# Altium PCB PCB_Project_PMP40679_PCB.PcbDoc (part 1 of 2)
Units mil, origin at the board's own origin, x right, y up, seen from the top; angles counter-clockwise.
Board outline 5118.11 x 3543.31 mil, 2 copper layers (Top Layer, Bottom Layer), stack 64.8 mil thick; 113 components, 55 nets, 272 pads, 364 vias.
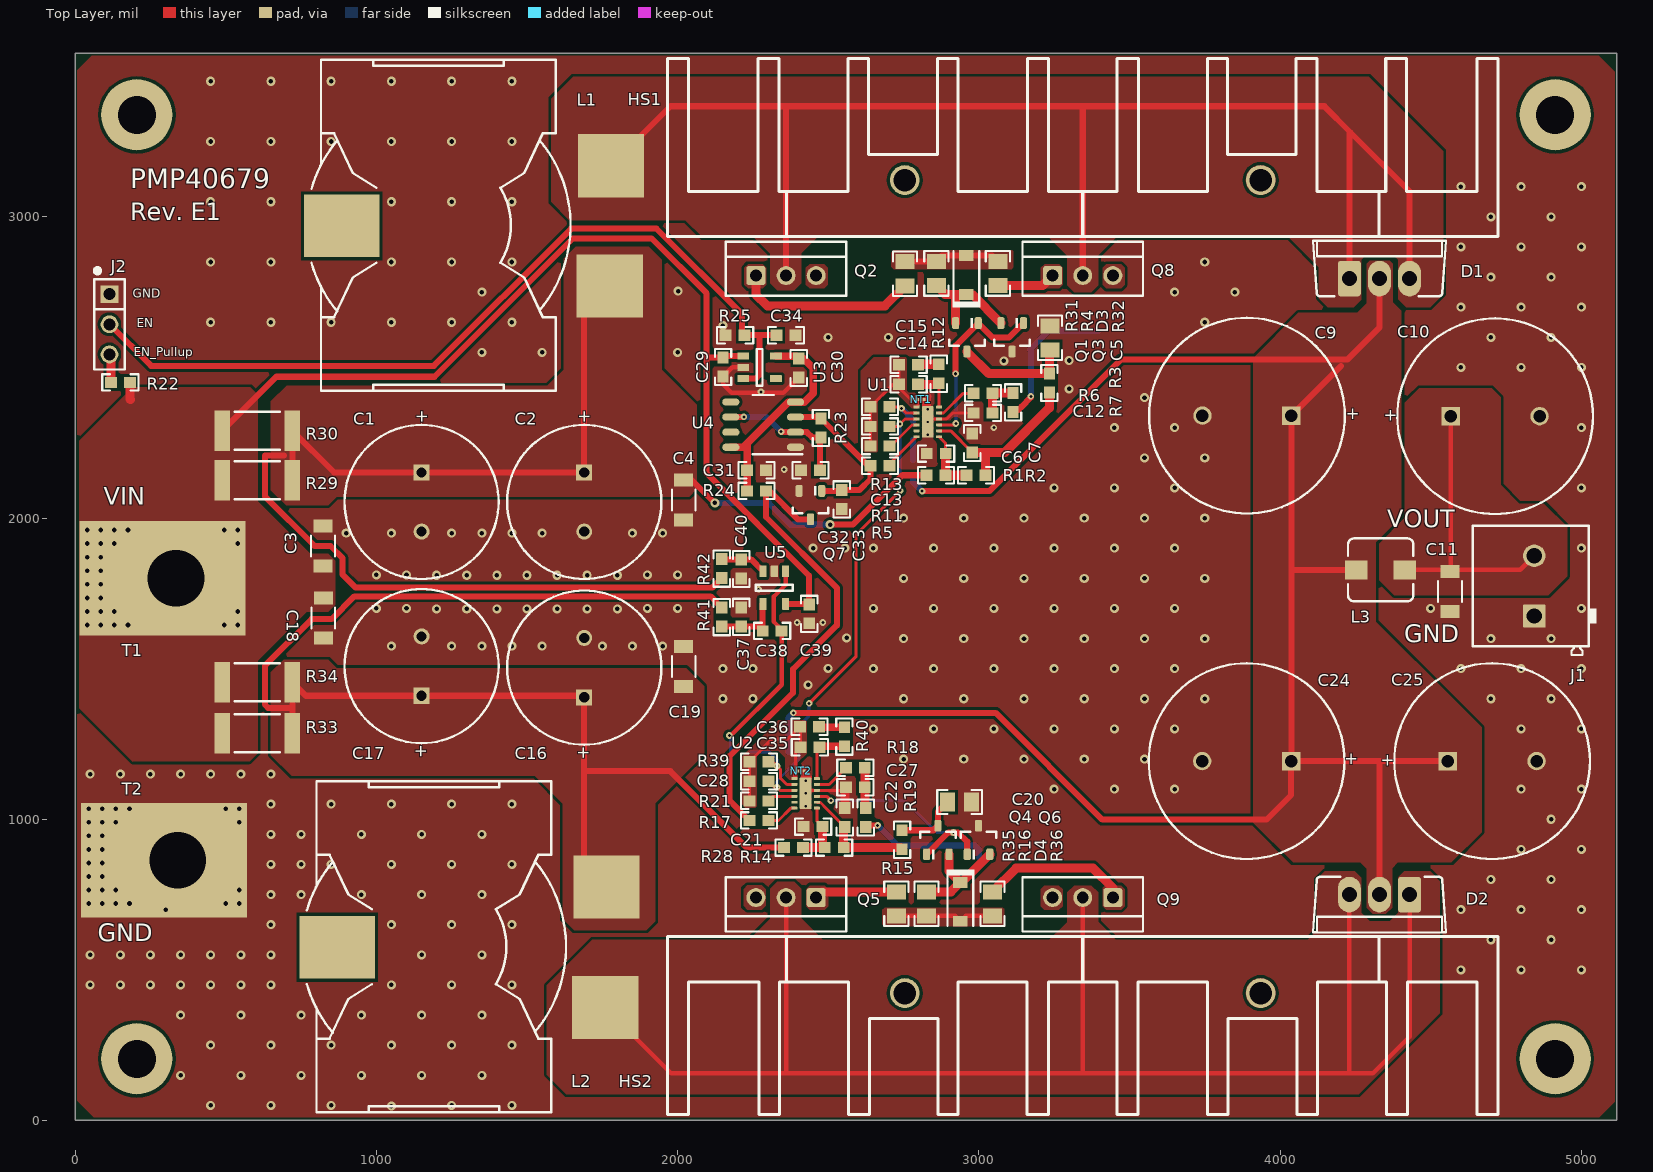
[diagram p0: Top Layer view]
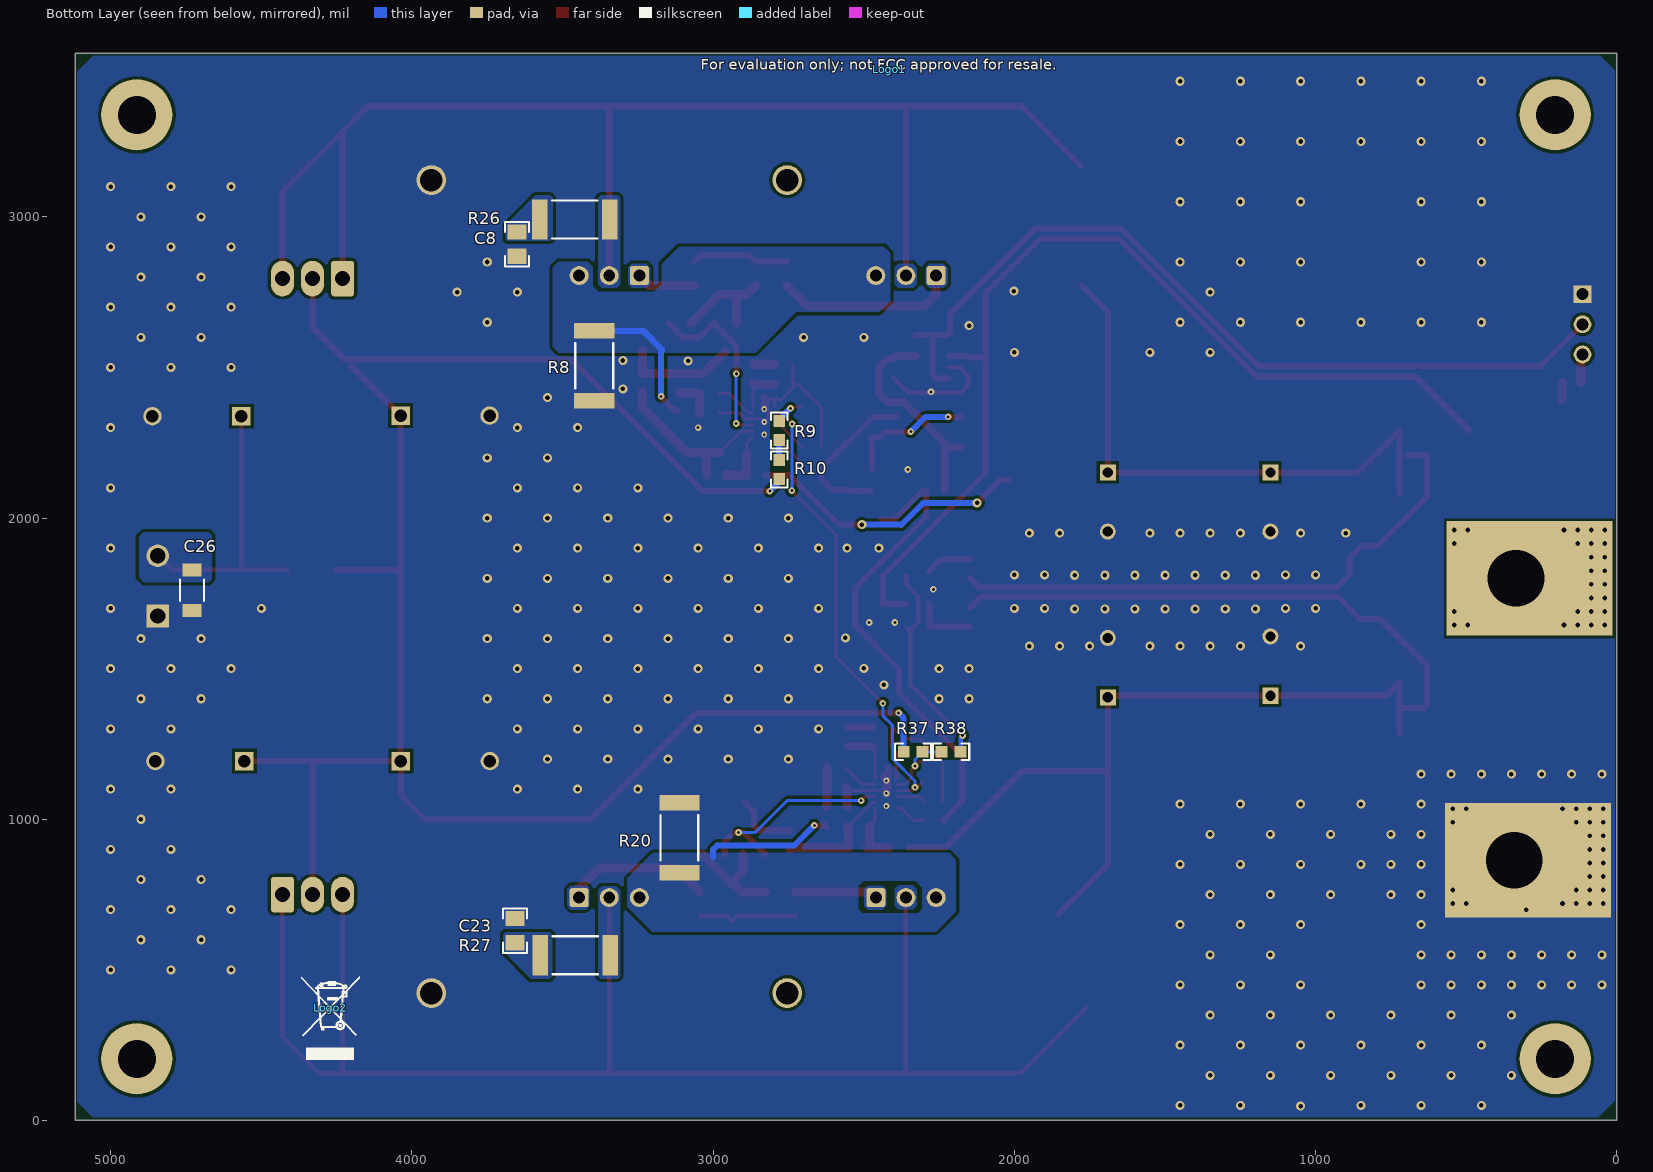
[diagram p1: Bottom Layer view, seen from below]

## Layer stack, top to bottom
Top Solder: solder mask 0.4, Solder Resist, Dk 3.5
Top Layer: signal copper 2.8
Dielectric1: core 59.2, FR-4, Dk 4.8
Bottom Layer: signal copper 2.8
Bottom Solder: solder mask 0.4, Solder Resist, Dk 3.5

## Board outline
0,0 5118.11,0 5118.11,3543.31 0,3543.31

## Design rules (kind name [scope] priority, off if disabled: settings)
AcuteAngle [All] p1: minimum=4.50000000000000E+0001 checktracksonly=FALSE
AssemblyTestPointUsage [All] p1: valid=2
Clearance Clearance_BoardEdge_MountingHoles [OnCopper and InComponentClass('Mounting Holes') vs IsKeepOut] p1: gap=40 ignorepadtopadclearanceinfootprint=FALSE except(0: Arc-Hole Track-Hole SMDPad-Hole THPad-Hole Via-Hole Fill-Hole Poly-Hole Region-Hole Text-Hole)
Clearance Clearance_BoardEdge_Poly [OnCopper and InPoly vs IsKeepOut] p2: gap=25 ignorepadtopadclearanceinfootprint=FALSE except(0: Arc-Hole Track-Hole SMDPad-Hole THPad-Hole Via-Hole Fill-Hole Poly-Hole Region-Hole Text-Hole)
Clearance Clearance_BoardEdge [OnCopper and Not InComponentClass('Logo') and not InComponentClass('FiducialMark') and not InRegion(1000,500,4000,800) and Not IsKeepout vs IsKeepOut] p3: gap=5 ignorepadtopadclearanceinfootprint=FALSE except(0: Arc-Hole Track-Hole SMDPad-Hole THPad-Hole Via-Hole Fill-Hole Poly-Hole Region-Hole Text-Hole)
Clearance Clearance_Poly [InPolygon] p4: gap=10 ignorepadtopadclearanceinfootprint=FALSE except(0: Arc-Hole Track-Hole SMDPad-Hole THPad-Hole Via-Hole Fill-Hole Poly-Hole Region-Hole Text-Hole)
Clearance [All] p5: gap=7 ignorepadtopadclearanceinfootprint=FALSE
ComponentClearance ComponentClearance_Logo [All] p1: gap=10 collisioncheckmode=3 verticalgap=10 showdistances=TRUE
ComponentClearance ComponentClearance_ScrewToNut [(HasFootprint('NY PMS 440 0025 PH')) vs (HasFootprint('Keystone_1902C'))] p2: gap=5 collisioncheckmode=3 verticalgap=10 showdistances=FALSE
ComponentClearance ComponentClearance_MountingHoles [InComponentClass('Mounting Holes')] p3: gap=10 collisioncheckmode=3 verticalgap=100000 showdistances=FALSE
ComponentClearance ComponentClearance_SmallPassives [HasFootprint('0201*') or HasFootprint('0402*') or HasFootprint('0508') or HasFootprint('0603*') or HasFootprint('0612') or HasFootprint('0805*') or HasFootprint('0815*') or HasFootprint('0830*') or HasFootprint('1206*') or HasFootprint('1210*') or HasFootprint('1808*') or HasFootprint('1812*') or HasFootprint('1825*') or HasFootprint('2010*') or HasFootprint('2220*') or HasFootprint('2225*') or HasFootprint('2512*') or HasFootprint('2728*') or HasFootprint('3518*') vs HasFootprint('0201*') or HasFootprint('0402*') or HasFootprint('0508') or HasFootprint('0603*') or HasFootprint('0612') or HasFootprint('0805*') or HasFootprint('0815*') or HasFootprint('0830*') or HasFootprint('1206*') or HasFootprint('1210*') or HasFootprint('1808*') or HasFootprint('1812*') or HasFootprint('1825*') or HasFootprint('2010*') or HasFootprint('2220*') or HasFootprint('2225*') or HasFootprint('2512*') or HasFootprint('2728*') or HasFootprint('3518*')] p4: gap=10 collisioncheckmode=3 verticalgap=10 showdistances=FALSE
ComponentClearance ComponentClearance_THtoSMT [IsThruComponent vs IsSMTComponent] p5: gap=10 collisioncheckmode=3 verticalgap=100000 showdistances=FALSE
ComponentClearance ComponentClearance_THtoTH [IsThruComponent vs IsThruComponent] p6: gap=10 collisioncheckmode=3 verticalgap=100000 showdistances=FALSE
ComponentClearance [All] p7: gap=10 collisioncheckmode=3 verticalgap=10 showdistances=FALSE
DiffPairsRouting [All] p1: maxlimit=100 minlimit=10 mostfreqgap=10 toplayer_minwidth=15 toplayer_maxwidth=15 toplayer_prefwidth=15 bottomlayer_minwidth=15 bottomlayer_maxwidth=15 bottomlayer_prefwidth=15 maxuncoupledlength=1000
FabricationTestPointUsage TestPointUsage [All] p1: valid=2 allowmultiple=FALSE
FabricationTestpoint Testpoint [All] p1: side=3 testpointundercomponent=TRUE minsize=40 maxsize=100 preferedsize=60 minholesize=0 maxholesize=40 preferedholesize=32 testpointgrid=1 allowsidetop=TRUE allowsidebottom=TRUE usegrid=TRUE gridtolerance=0.01
FanoutControl Fanout_LCC [IsLCC] p1: bgadir=Out bgaviamode=Centered fanoutstyle=Auto fanoutdirection=Alternating viagrid=1 // Fanout_LCC (Default Rule)
FanoutControl Fanout_BGA [IsBGA] p2: bgadir=Out bgaviamode=Centered fanoutstyle=Auto fanoutdirection=Alternating viagrid=1 // Fanout_BGA (Default Rule)
FanoutControl Fanout_Default [All] p4: bgadir=Out bgaviamode=Centered fanoutstyle=Auto fanoutdirection=Alternating viagrid=1 // Fanout_Default (Default Rule)
FanoutControl Fanout_Small [(CompPinCount < 5)] p5: bgadir=Out bgaviamode=Centered fanoutstyle=Auto fanoutdirection=OutThenIn viagrid=1 // Fanout_Small (Default Rule)
Height [All] p1: minheight=0 maxheight=1574.8 prefheight=500
HoleSize [All] p1: absolutevalues=TRUE maxlimit=251 minlimit=6 maxpercent=80.000 minpercent=20.000
MinimumAnnularRing [All] p1: minimumring=3
MinimumSolderMaskSliver MinimumSolderMaskSliver_Logo [InComponentClass('Logo') vs InComponentClass('Logo')] p1: minsoldermaskwidth=0.7
MinimumSolderMaskSliver [All] p2: minsoldermaskwidth=0
PlaneConnect [All] p1: planeconnectstyle=Direct reliefexpansion=10 reliefentries=4 reliefconductorwidth=10 reliefairgap=10
PolygonConnect [All] p1: connectstyle=Direct reliefconductorwidth=10 reliefentries=4 polygonreliefangle="90 Angle" airgapwidth=10
RoutingCorners [All] p1: cornerstyle=45-Degree minsetback=10 maxsetback=100
RoutingVias [All] p1: holewidth=16 width=34 viastyle="Through Hole" minholewidth=6 minwidth=16 maxholewidth=40 maxwidth=65
SMDToCorner [All] p1: distance=0
SilkToBoardRegionClearance [Not ((IsComment or IsDesignator) And (Hide <> 'False')) and not InRegion(1000,500,4000,800)] p1:
SilkToSilkClearance [All] p1: silktosilkclearance=0
SilkToSolderMaskClearance SilkscreenOverComponentPads [IsPad] p1: minsilkscreentomaskgap=0 clearancetoexposedcopper=TRUE
SolderMaskExpansion [All] p1: expansion=3
Width [All] p1: maxlimit=100 minlimit=6 preferedwidth=10 checkconnectedcopper=TRUE
13 further rules are at their usual default settings.

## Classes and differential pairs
component class PCB_Project_PMP40679_BlankSheet: !PCB1 C1 C2 C3 C4 C5 C6 C7 C8 C9 C10 C11 C12 C13 C14 C15 C16 C17 C18 C19 C20 C21 C22 C23 C24 C25 C26 C27 C28 C35 C36 D1 D2 D3 D4 HS1 HS2 J1 L1 L2 L3 NT1 NT2 Q1 Q2 Q3 Q4 Q5 Q6 Q8 Q9 R1 R2 R3 R4 R5 R6 R7 R8 R9 R10 R11 R12 R13 R14 R15 R16 R17 R18 R19 R20 R21 R26 R27 R28 R29 R30 R31 R32 R33 R34 R35 R36 R37 R38 R39 R40 T1 T2 U1 U2
component class Header: J2
component class PCB_Project_PMP40679_EVM_Hardware: !PCB1 C29 C30 C31 C32 C33 C34 C37 C38 C39 C40 J2 Logo1 Logo2 Q7 R22 R23 R24 R25 R41 R42 U3 U4 U5

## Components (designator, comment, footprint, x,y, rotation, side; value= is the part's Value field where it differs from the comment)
C1 "EKY-250ELL152MK25S" Chemi-Con_1250x2500 1150,2053.43 r270 top value=1500uF
C2 "EKY-250ELL152MK25S" Chemi-Con_1250x2500 1690,2053.43 r270 top value=1500uF
C3 "GRM31CR71E475KA88L" 1206_180 823,1907 r90 top value=4.7uF
C4 "GRM31CR71E475KA88L" 1206_180 2020,2060 r270 top value=4.7uF
C5 "GRM21BR71E225KA73L" 0805_HV 3236.5,2598 r90 top value=2.2uF
C6 "GRM188R71H104KA93D" 0603 2858.5,2214 r180 top value=0.1uF
C7 "GRM188R71E105KA12D" 0603 2978.5,2249 r90 top value=1uF
C8 "GRM2165C2A102JA01D" 0805_HV 3651,2909 r270 bottom value=1000pF
C9 "EKY-630ELL681ML25S" KY_1600x2500 3890,2340 r180 top value=680uF
C10 "EKY-630ELL681ML25S" KY_1600x2500 4714,2338 r0 top value=680uF
C11 "GRM31CR72A105KA01L" 1206_180 4564,1756 r270 top value=1uF
C12 "GRM1885C1H182JA01D" 0603 3013.5,2349 r180 top value=1800pF
C13 "GRM188R71A684KA61D" 0603 2672.01,2304 r180 top value=0.68uF
C14 "GRM1885C1H471JA01D" 0603 2767.01,2444 r180 top value=470pF
C15 "GRM188R71C223KA01D" 0603 2767.01,2509 r180 top value=0.022uF
C16 "EKY-250ELL152MK25S" Chemi-Con_1250x2500 1690,1503.43 r90 top value=1500uF
C17 "EKY-250ELL152MK25S" Chemi-Con_1250x2500 1150,1508.43 r90 top value=1500uF
C18 "GRM31CR71E475KA88L" 1206_180 824,1668 r270 top value=4.7uF
C19 "GRM31CR71E475KA88L" 1206_180 2020,1507 r90 top value=4.7uF
C20 "GRM21BR71E225KA73L" 0805_HV 2936,1057 r0 top value=2.2uF
C21 "GRM188R71H104KA93D" 0603 2450,975.94 r180 top value=0.1uF
C22 "GRM188R71E105KA12D" 0603 2555,1005.94 r90 top value=1uF
C23 "GRM2165C2A102JA01D" 0805_HV 3658,630 r90 bottom value=1000pF
C24 "EKY-630ELL681ML25S" KY_1600x2500 3889,1193 r180 top value=680uF
C25 "EKY-630ELL681ML25S" KY_1600x2500 4704,1193 r0 top value=680uF
C26 "GRM31CR72A105KA01L" 1206_180 4730,1760 r270 bottom value=1uF
C27 "GRM1885C1H182JA01D" 0603 2590,1105.94 r180 top value=1800pF
C28 "GRM188R71A684KA61D" 0603 2270,1125.94 r180 top value=0.68uF
C29 "GRM188R71H104KA93D" 0603 2151,2501 r270 top value=0.1uF
C30 "GRM188Z71A475ME15D" 0603 2402,2498 r270 top value=4.7uF
C31 "GRM188R71H104KA93D" 0603 2262,2159 r0 top value=0.1uF
C32 "GRM1885C1H102FA01J" 0603 2441,2159 r180 top value=1000pF
C33 "GRM1885C1H220JA01D" 0603 2545,2062 r270 top value=22pF
C34 "GRM188R71H104KA93D" 0603 2360,2607 r0 top value=0.1uF
C35 "GRM1885C1H471JA01D" 0603 2439,1239 r180 top value=470pF
C36 "GRM188R71C223KA01D" 0603 2438,1307 r180 top value=0.022uF
C37 "GRM188R71E105KA12D" 0603 2211,1672 r90 top value=1uF
C38 "GRM188R71H473KA61D" 0603 2314,1625 r0 top value=0.047uF
C39 "GRM188R71E105KA12D" 0603 2437,1682 r270 top value=1uF
C40 "GRM188R71E105KA12D" 0603 2211,1831 r270 top value=1uF
D1 "TST20L60CW" TO-220AB 4330,2795 r0 top
D2 "TST20L60CW" TO-220AB 4330,750 r180 top
D3 "BAT54T1G" SOD-123 2959,2807 r90 top value=30V
D4 "BAT54T1G" SOD-123 2939,726 r270 top value=30V
HS1 "FL12-020" PCBComponent_1 3345,2935 r0 top locked
HS2 "FL12-020" PCBComponent_1 3345,610 r180 top locked
J1 "1715721" PhoenixContact_1715721 4844,1774.65 r90 top
J2 "PEC03SAAN" CONN_PEC03SAAN 114,2643 r270 top
L1 "SER2915L-332KL" SER2915L 1210,2970 r180 top value=3.3uH
L2 "SER2915L-332KL" SER2915L 1195,575 r180 top value=3.3uH
L3 "744316033" WE-HCI_5040 4334,1828 r90 top value=330nH
Logo1 "FCC disclaimer" FCC_disclaimer 2415,3490 r180 bottom
Logo2 "WEEE logo" WEEE_Minimum 4272,374 r180 bottom
NT1 "Net-Tie" Net-Tie_10mil 2808.5,2394 r180 top net-tie
NT2 "Net-Tie" Net-Tie_10mil 2410,1160.94 r180 top net-tie
Q1 "MMBT2222ALT1G" SOT-23 2960.5,2600 r270 top value="40 V"
Q2 "CSD18533KCS" KCS0003B 2360,2805 r90 top value=60V
Q3 "MMBT4403" SOT-23 3110.5,2600 r270 top value="40 V"
Q4 "MMBT2222ALT1G" SOT-23 2864,931 r90 top value="40 V"
Q5 "CSD18533KCS" KCS0003B 2360,740 r270 top value=60V
Q6 "MMBT4403" SOT-23 2999,931 r90 top value="40 V"
Q7 "2N7002ET1G" SOT-23 2441,2043 r270 top value=60V
Q8 "CSD18533KCS" KCS0003B 3345,2805 r90 top value=60V
Q9 "CSD18533KCS" KCS0003B 3345,740 r270 top value=60V
R1 "RC0603JR-070RL" 0603 2857.51,2142 r180 top value=0
R2 "RC0603JR-070RL" 0603 2990.51,2142 r180 top value=0
R3 "RC0603JR-070RL" 0603 3234.5,2448 r270 top value=0
R4 "RC0805FR-076R2L" 0805_HV 2859,2812 r90 top value=6.20
R5 "RC0603FR-07100RL" 0603 2672.01,2174 r0 top value=100
R6 "RC0603FR-07510RL" 0603 3013.5,2414 r0 top value=510
R7 "RC0603FR-07200RL" 0603 3113.5,2384 r270 top value=200
R8 "ERJ-M1WTF1M0U" 2512 3395,2505 r90 bottom value=0.001
R9 "RC0603FR-07100KL" 0603 2781,2291 r270 bottom value=100k
R10 "RC0603FR-0730RL" 0603 2781,2161 r270 bottom value=30.0
R11 "RC0603FR-07147KL" 0603 2672.01,2239 r0 top value=147k
R12 "RC0603FR-0739KL" 0603 2867.01,2479 r270 top value=39.0k
R13 "RC0603FR-072K21L" 0603 2672.01,2369 r0 top value=2.21k
R14 "RC0603JR-070RL" 0603 2520,905.94 r180 top value=0
R15 "RC0603JR-070RL" 0603 2745,932 r270 top value=0
R16 "RC0805FR-076R2L" 0805_HV 2826,719 r270 top value=6.20
R17 "RC0603FR-07100RL" 0603 2270,995.94 r0 top value=100
R18 "RC0603FR-07510RL" 0603 2590,1170.94 r0 top value=510
R19 "RC0603FR-07200RL" 0603 2625,1005.94 r270 top value=200
R20 "ERJ-M1WTF1M0U" 2512 3112,939 r270 bottom value=0.001
R21 "RC0603FR-07147KL" 0603 2270,1060.94 r0 top value=147k
R22 "RC0603FR-07100KL" 0603 150,2450 r0 top value=100k
R23 "RC0603FR-074K75L" 0603 2476,2299 r90 top value=4.75k
R24 "RC0603FR-071K8L" 0603 2262,2090 r180 top value=1.80k
R25 "RC0603FR-0711KL" 0603 2191,2607 r0 top value=11.0k
R26 "CRCW25127R50FKEG" 2512 3459,2991 r180 bottom value=7.50
R27 "CRCW25127R50FKEG" 2512 3458,548 r180 bottom value=7.50
R28 "RC0603JR-070RL" 0603 2385,905.94 r180 top value=0
R29 "ERJ-M1WTF4M0U" 2512 605,2125 r0 top value=0.004
R30 "ERJ-M1WTF4M0U" 2512 605,2290 r0 top value=0.004
R31 "RC0805FR-072R2L" 0805_HV 2755,2811 r270 top value=2.20
R32 "RC0805FR-072R2L" 0805_HV 3063,2812 r270 top value=2.20
R33 "ERJ-M1WTF4M0U" 2512 605,1285 r0 top value=0.004
R34 "ERJ-M1WTF4M0U" 2512 605,1455 r0 top value=0.004
R35 "RC0805FR-072R2L" 0805_HV 2726,719 r90 top value=2.20
R36 "RC0805FR-072R2L" 0805_HV 3045,719 r90 top value=2.20
R37 "RC0603FR-07100KL" 0603 2336,1224 r0 bottom value=100k
R38 "RC0603FR-07200KL" 0603 2210,1224 r180 bottom value=200k
R39 "RC0603FR-072K21L" 0603 2270,1190.94 r0 top value=2.21k
R40 "RC0603FR-0739KL" 0603 2554,1274 r270 top value=39.0k
R41 "RC0603FR-07100RL" 0603 2147,1671 r270 top value=100
R42 "RC0603FR-07100RL" 0603 2147,1832 r90 top value=100
T1 "CB35-36-CY" CB35-36-CY#1 335,1800 r0 top
T2 "CB35-36-CY" CB35-36-CY#2 340,875 r0 top
U1 "LM5155DSSR" DSS0012B 2830.51,2319 r180 top
U2 "LM5155DSSR" DSS0012B 2425,1085.94 r180 top
U3 "TPS70950DBVR" DBV0005A_N 2272,2500 r0 top
U4 "LMC555CMX/NOPB" D0008A_N 2284,2310 r180 top
U5 "TLV271IDBVR" DBV0005A_N 2321,1769 r270 top

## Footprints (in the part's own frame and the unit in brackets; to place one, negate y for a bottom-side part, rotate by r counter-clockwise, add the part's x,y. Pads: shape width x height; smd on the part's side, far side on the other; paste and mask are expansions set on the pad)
0603 [mm] "0603 from SM-752 data"
  rect 1x0.95 smd: 1(-0.8,0) 2(0.8,0)
  silkscreen extent -1.52,-0.69 1.52,0.69, body extent -0.87,-0.47 0.87,0.47, height 1
0805_HV [mil] "0805 with 30mil clearance between pads"
  rect 50x63 smd: 1(-40,0) 2(40,0)
  silkscreen extent -74,-40 74,40, body extent -43,-29 43,29, height 57
1206_180 [mm] "1206_180"
  rect 1.1x1.6 smd: 1(-1.7,0) 2(1.7,0)
  silkscreen extent -0.9,-1 0.9,1, body extent -1.75,-0.95 1.75,0.95, height 1.8
2512 [mm] "Chip Resistor, Body 6.3x3.2mm, IPC Medium Density"
  rect 1.3x3.4 smd: 1(-2.95,0) 2(2.95,0)
  silkscreen extent -1.9,-1.6 1.9,1.6, body extent -3.22,-1.67 3.22,1.67, height 0.71
CB35-36-CY#1 [mil] "Terminal 50A Lug"
  rect 550x380 hole 188 copper offset -45,0 paste-190: 1(0,0)
  body extent -960,-189 230,191, height 614
CB35-36-CY#2 [mil] "Terminal 50A Lug"
  rect 550x380 hole 188 copper offset -45,0 paste-190: 1(0,-10.75)
  body extent -960,-189 230,191, height 614
Chemi-Con_1250x2500 [mm] "TH, 2-Leads, Dia 12.5mm, Lead Sapcing 5mm"
  rect 1.35x1.35 hole 0.85: 1(-2.5,0)
  round 1.35 hole 0.85: 2(2.5,0)
  silkscreen extent -6.5,-6.5 6.5,6.5, body extent -6.5,-6.5 6.51,6.5, height 26.5
CONN_PEC03SAAN [mm] "SULLINS"
  rect 1.5x1.5 hole 1.016: 1(-2.54,0)
  round 1.5 hole 1.016: 2(0,0) 3(2.54,0)
  silkscreen extent -4.72,-1.27 3.81,1.27, body extent -3.84,-1.3 3.84,1.3, height 8.38
D0008A_N [mm] "SOIC, 8-Leads, Body 4.9x3.9mm, Pitch 1.27mm, IPC Medium Density"
  oval 1.45x0.6 smd: 1(-2.725,1.905) 2(-2.725,0.635) 3(-2.725,-0.635) 4(-2.725,-1.905) 5(2.725,-1.905) 6(2.725,-0.635) 7(2.725,0.635) 8(2.725,1.905)
  silkscreen extent -3.3,-2.5 0.9,2.5, body extent -3,-2.45 3,2.45, height 1.63
DBV0005A_N [mm] "SOT23, 5-Leads, Body 2.9x1.6mm, Pitch 0.95mm, Lead Span 2.8mm, IPC Medium Density"
  rrect17% 1x0.6 smd: 1(-1.375,0.95) 2(-1.375,0) 3(-1.375,-0.95) 4(1.375,-0.95) 5(1.375,0.95)
  silkscreen extent -0.25,-1.55 0.25,1.55, body extent -1.42,-1.46 1.42,1.46, height 1.09
DSS0012B [mm] "WSON-10"
  rrect40% 0.5x0.25 smd: 1(-0.95,1.25) 2(-0.95,0.75) 3(-0.95,0.25) 4(-0.95,-0.25) 5(-0.95,-0.75) 6(-0.95,-1.25) 7(0.95,-1.25) 8(0.95,-0.75) 9(0.95,-0.25) 10(0.95,0.25) 11(0.95,0.75) 12(0.95,1.25)
  rrect11% 1x2.65 smd paste-0.5: 13(0,0)
  body extent -1,-1.5 1,1.5, height 0.81
FCC_disclaimer [mil]
KCS0003B [mm] "Flange Mount, 3-Leads, Body 10.16x4.51mm, Pitch 2.54mm"
  rrect25% 1.6x1.6 hole 1: 1(0,2.54)
  round 1.6 hole 1: 2(0,0) 3(0,-2.54)
  silkscreen extent -1.71,-5.08 2.86,5.08, body extent -1.71,-5.09 2.86,5.08, height 18.63
KY_1600x2500 [mm] "TH, 2-Leads, Dia 16mm, Pin Spacing 7.5mm"
  rect 1.55x1.55 hole 1.05: 1(-3.75,0)
  round 1.55 hole 1.05: 2(3.75,0)
  silkscreen extent -8.25,-8.25 8.25,8.25, body extent -8.25,-8.26 8.25,8.26, height 26.5
Net-Tie_10mil [mil] "10mil net tie, no solder mask opening, no solder paste"
  rect 10x10 smd paste-5 mask-5: 1(-10,0) 2(10,0)
  Top Layer region: -6,5 6,5 6,-5 -6,-5
PCBComponent_1 [mm]
  round 2.5 hole 1.9: 1(-15,4.75) 2(15,4.75)
  silkscreen extent -35,0 35,15, body extent -35,0 35,15.08, height 40
PhoenixContact_1715721 [mm] "Phoenix Contact 1715721 used on LM3445 design from Longmont"
  rrect5% 1.905x1.905 hole 1.3: 1(-2.54,0)
  round 1.9 hole 1.3: 2(2.54,0)
  silkscreen extent -5.82,-5.25 5.08,5.2, body extent -5.82,-4.6 5.08,5.2, height 14.2
SER2915L [mm] "COILCRAFT"
  rect 5.59x5.33 smd: 1(-14.355,5.075) 2(-14.455,-5.075)
  rect 6.35x5.28 smd: 3(8.25,0)
  silkscreen extent -11.04,-14 10.81,13.9, body extent -16.7,-14.05 11.22,13.85, height 15.4
SOD-123 [mm] "On Semi recommended land pattern"
  rect 0.915x1.22 smd: 1(-1.637,0) 2(1.637,0)
  silkscreen extent -2.74,-1.17 2.03,1.17, body extent -1.93,-0.9 1.93,0.9, height 1.35
SOT-23 [mm] "SOT23, 3-Leads, Body 2.9x1.3mm, Pitch 0.95mm, Lead Span 2.5mm, IPC Medium Density"
  rrect50% 1x0.6 smd: 1(-1.2,0.95) 2(-1.2,-0.95) 3(1.2,0)
  silkscreen extent -1.63,-1.5 0.7,1.5, body extent -1.16,-1.45 1.21,1.45, height 1
TO-220AB [mil] "Copied from Altium's version of TO3B"
  rrect25% 76x118.11 hole 50: 1(-100,0)
  oval 76x118.11 hole 50: 2(0,0) 3(100,0)
  silkscreen extent -221,-59 221,126, body extent -221,-59 221,126, height 765
WE-HCI_5040 [mm] "SMD, 2-Leads, Body 5.5x5.3mm"
  rect 1.6x1.9 smd: 1(0,2.05) 2(0,-2.05)
  silkscreen extent -2.65,-2.75 2.65,2.75, body extent -2.65,-2.79 2.65,2.79, height 3.95
WEEE_Minimum [mil] "WEEElie bin"
  silkscreen extent -95,-172 99,104

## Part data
C1 C2 C16 C17: library part CMP-0010401-1, "CAP, AL, 1500 uF, 25 V, +/- 20%, TH", Cap_Case=12.5x25, Manufacturer=Chemi-Con, Tolerance_%=20%, Value1=Unknown, Value2=25V, ValueDisplayed=1500uF
C3 C4 C18 C19: library part CMP-0008967-2, "CAP, CERM, 4.7 uF, 25 V, +/- 10%, X7R, 1206", Cap_Case=1206, Manufacturer=MuRata, Supplier Part Number 1=490-1809-1-ND, TempCo=X7R, Tolerance_%=10%, Value1=Unknown, Value2=25V, ValueDisplayed=4.7uF
C5 C20: library part CMP-0008342-2, "CAP, CERM, 2.2 uF, 25 V, +/- 10%, X7R, 0805", Cap_Case=0805, Manufacturer=MuRata, Supplier Part Number 1=490-3331-1-ND, TempCo=X7R, Tolerance_%=10%, Value1="0.005 ohm", Value2=25V, ValueDisplayed=2.2uF
C6 C21 C29 C31 C34: library part CMP-0007434-4, "CAP, CERM, 0.1 uF, 50 V, +/- 10%, X7R, 0603", Cap_Case=0603, Manufacturer=MuRata, Supplier Part Number 1=490-1519-1-ND, TempCo=X7R, Tolerance_%=10%, Value1=Unknown, Value2=50V, ValueDisplayed=0.1uF
C7 C22 C37 C39 C40: library part CMP-0007405-4, "CAP, CERM, 1 uF, 25 V, +/- 10%, X7R, 0603", Cap_Case=0603, Manufacturer=MuRata, Supplier Part Number 1=490-5307-1-ND, TempCo=X7R, Tolerance_%=10%, Value1=Unknown, Value2=25V, ValueDisplayed=1uF
C8 C23: library part CMP-0008094-2, "CAP, CERM, 1000 pF, 100 V, +/- 5%, C0G/NP0, 0805", Cap_Case=0805, Manufacturer=MuRata, Supplier Part Number 1=GRM2165C2A102JA01D-ND, TempCo=C0G/NP0, Tolerance_%=5%, Value1=Unknown, Value2=100V, ValueDisplayed=1000pF
C9 C10 C24 C25: library part CMP-0009872-2, "CAP, AL, 680 uF, 63 V, +/- 20%, 0.025 ohm, TH", Cap_Case=16x25mm, Manufacturer=Chemi-Con, Supplier Part Number 1=EKY-630ELL681ML25S-ND, Tolerance_%=20%, Value1="0.025 ohm", Value2=63V, ValueDisplayed=680uF
C11 C26: library part CMP-0008970-2, "CAP, CERM, 1 uF, 100 V, +/- 10%, X7R, 1206", Cap_Case=2220, Manufacturer=MuRata, Supplier Part Number 1=490-3909-1-ND, TempCo=X7R, Tolerance_%=10%, Value1=Unknown, Value2=100V, ValueDisplayed=1uF
C12 C27: library part CMP-0007192-4, "CAP, CERM, 1800 pF, 50 V, +/- 5%, C0G/NP0, 0603", Cap_Case=0603, Manufacturer=MuRata, Supplier Part Number 1=490-1457-1-ND, TempCo=C0G/NP0, Tolerance_%=5%, Value1=Unknown, Value2=50V, ValueDisplayed=1800pF
C13 C28: library part CMP-0007375-4, "CAP, CERM, 0.68 uF, 10 V, +/- 10%, X7R, 0603", Cap_Case=0603, Manufacturer=MuRata, Supplier Part Number 1=GRM188R71A684KA61D-ND, TempCo=X7R, Tolerance_%=10%, Value1=Unknown, Value2=10V, ValueDisplayed=0.68uF
C14 C35: library part CMP-0007221-4, "CAP, CERM, 470 pF, 50 V, +/- 5%, C0G/NP0, 0603", Cap_Case=0603, Manufacturer=MuRata, Supplier Part Number 1=490-1443-1-ND, TempCo=C0G/NP0, Tolerance_%=5%, Value1=Unknown, Value2=50V, ValueDisplayed=470pF
C15 C36: library part CMP-0007388-4, "CAP, CERM, 0.022 uF, 16 V, +/- 10%, X7R, 0603", Cap_Case=0603, Manufacturer=MuRata, Supplier Part Number 1=490-1527-1-ND, TempCo=X7R, Tolerance_%=10%, Value1=Unknown, Value2=16V, ValueDisplayed=0.022uF
C30: library part CMP-0007498-4, "CAP, CERM, 4.7 uF, 10 V, +/- 20%, X7R, 0603", Cap_Case=0603, Manufacturer=MuRata, TempCo=X7R, Tolerance_%=20%, Value1=Unknown, Value2=10V, ValueDisplayed=4.7uF
C32: library part CMP-0007172-4, "CAP, CERM, 1000 pF, 50 V, +/- 1%, C0G/NP0, 0603", Cap_Case=0603, Manufacturer=MuRata, Supplier Part Number 1=490-6377-1-ND, TempCo=C0G/NP0, Tolerance_%=1%, Value1=Unknown, Value2=50V, ValueDisplayed=1000pF
C33: library part CMP-0007196-4, "CAP, CERM, 22 pF, 50 V, +/- 5%, C0G/NP0, 0603", Cap_Case=0603, Manufacturer=MuRata, Supplier Part Number 1=490-1411-1-ND, TempCo=C0G/NP0, Tolerance_%=5%, Value1=Unknown, Value2=50V, ValueDisplayed=22pF
C38: library part CMP-0007457-4, "CAP, CERM, 0.047 uF, 50 V, +/- 10%, X7R, 0603", Cap_Case=0603, Manufacturer=MuRata, Supplier Part Number 1=490-3287-1-ND, TempCo=X7R, Tolerance_%=10%, Value1=Unknown, Value2=50V, ValueDisplayed=0.047uF
D1 D2: library part CMP-0028764-3, "Diode, Schottky, 60 V, 20 A, TH", Manufacturer="Taiwan Semiconductor", PartNumber=TST20L60CWC0G, Supplier Part Number 1=TST20L60CWC0G-ND
D3 D4: library part CMP-0028457-2, "Diode, Schottky, 30 V, 0.2 A, SOD-123", Manufacturer="ON Semiconductor", Value1=0.2A, Value2=0.8V
HS1 HS2: library part CMP-0087085-1, "HEATSINK FOR 3 TO-220", Manufacturer="FL Heatsink"
J1: library part CMP-0055471-1, "Terminal Block, 5.08 mm, 2x1, TH", Color=Green, Current_A=17.5A, Manufacturer="Phoenix Contact", Supplier Part Number 1=277-1263-ND, Voltage_V=400V
J2: library part CMP-0002338-1, "Header, 100mil, 3x1, Tin, TH", Color=Black, Current_A=3A, Manufacturer="Sullins Connector Solutions", Supplier Part Number 1=S1012E-03-ND, Voltage_V=1.8kV
L1 L2: library part CMP-0060859-1, "Inductor, Shielded E Core, Ferrite, 3.3 uH, 30 A, 0.0015 ohm, SMD", Manufacturer=Coilcraft, Value1="0.0015 ohm", Value2=30A, ValueDisplayed=3.3uH
L3: library part CMP-0063948-1, "Inductor, Wirewound, 330 nH, 18.5 A, 0.00175 ohm, SMD", Manufacturer="Wurth Elektronik", Supplier Part Number 1=732-6173-1-ND, Value1="0.00175 ohm", Value2=18.5A, ValueDisplayed=330nH
Logo1: library part CMP-0074847-1, "FCC_disclaimer"
Logo2: library part CMP-0074769-1
NT1 NT2: "Single point connection between nets."
Q1 Q4: library part CMP-0000461-2, "Transistor, NPN, 40 V, 0.6 A, SOT-23", Manufacturer="ON Semiconductor", Supplier Part Number 1=MMBT2222ALT1GOSCT-ND, Value1="0.6 A"
Q2 Q5 Q8 Q9: library part CMP-0000814-1, "MOSFET, N-CH, 60 V, 100 A, KCS0003B (TO-220-3)", Alternate Manufacturer=None, Manufacturer="Texas Instruments", Supplier Part Number 1=296-35013-ND, Value1=0, Value2="28 nC"
Q3 Q6: library part CMP-0000327-2, "Transistor, PNP, 40 V, 0.6 A, SOT-23", Manufacturer="Fairchild Semiconductor", Supplier Part Number 1=MMBT4403FSCT-ND, Value1="0.6 A", Value2=500
Q7: library part CMP-0000772-1, "MOSFET, N-CH, 60 V, 0.26 A, SOT-23", Alternate Manufacturer=None, Manufacturer="ON Semiconductor", Supplier Part Number 1=2N7002ET1GOSCT-ND, Value2="0.81 nC"
R1 R2 R3 R14 R15 R28: library part CMP-0025885-5, "RES, 0, 5%, 0.1 W, 0603", Manufacturer=Yageo, Power_W=100mW, Supplier Part Number 1=311-0.0GRCT-ND, TempCo="200 ppm/C", Tolerance_%=5%, Value2=0.1W, Value_Code=0000, ValueDisplayed=0
R4 R16: library part CMP-0021950-2, "RES, 6.20, 1%, 0.125 W, 0805", Manufacturer="Yageo America", Power_W=125mW, Supplier Part Number 1=311-6.20CRCT-ND, TempCo="200 ppm/C", Tolerance_%=1%, Value2=0.125W, Value_Code=6R20, ValueDisplayed=6.20
R5 R17 R41 R42: library part CMP-0022736-4, "RES, 100, 1%, 0.1 W, 0603", Manufacturer=Yageo, Power_W=100mW, Supplier Part Number 1=311-100HRCT-ND, TempCo="100 ppm/C", Tolerance_%=1%, Value2=0.1W, Value_Code=100R, ValueDisplayed=100
R6 R18: library part CMP-0023163-5, "RES, 510, 1%, 0.1 W, 0603", Manufacturer=Yageo, Power_W=100mW, Supplier Part Number 1=311-510HRCT-ND, TempCo="100 ppm/C", Tolerance_%=1%, Value2=0.1W, Value_Code=510R, ValueDisplayed=510
R7 R19: library part CMP-0022902-5, "RES, 200, 1%, 0.1 W, 0603", Manufacturer=Yageo, Power_W=100mW, Supplier Part Number 1=311-200HRCT-ND, TempCo="100 ppm/C", Tolerance_%=1%, Value2=0.1W, Value_Code=200R, ValueDisplayed=200
R8 R20: library part CMP-0015817-2, "RES, 0.001, 1%, 1 W, 2512", Manufacturer=Panasonic, Power_W=1W, Supplier Part Number 1=P1.0NDCT-ND, TempCo=ppm/C, Tolerance_%=1%, Value_Code=1L000, ValueDisplayed=0.001
R9 R22 R37: library part CMP-0022735-5, "RES, 100 k, 1%, 0.1 W, 0603", Manufacturer=Yageo, Power_W=100mW, Supplier Part Number 1=311-100KHRCT-ND, TempCo="100 ppm/C", Tolerance_%=1%, Value2=0.1W, Value_Code=100k
R10: library part CMP-0023023-4, "RES, 30.0, 1%, 0.1 W, 0603", Manufacturer=Yageo, Power_W=100mW, Supplier Part Number 1=311-30.0HRCT-ND, TempCo="100 ppm/C", Tolerance_%=1%, Value2=0.1W, Value_Code=30R0, ValueDisplayed=30.0
R11 R21: library part CMP-0022800-4, "RES, 147 k, 1%, 0.1 W, 0603", Manufacturer=Yageo, Power_W=100mW, Supplier Part Number 1=311-147KHRCT-ND, TempCo="100 ppm/C", Tolerance_%=1%, Value2=0.1W, Value_Code=147k
R12 R40: library part CMP-0023073-5, "RES, 39.0 k, 1%, 0.1 W, 0603", Manufacturer=Yageo, Power_W=100mW, Supplier Part Number 1=311-39.0KHRCT-ND, TempCo="100 ppm/C", Tolerance_%=1%, Value2=0.1W, Value_Code=39k0, ValueDisplayed=39.0k
R13 R39: library part CMP-0022984-5, "RES, 2.21 k, 1%, 0.1 W, 0603", Manufacturer=Yageo, Power_W=100mW, Supplier Part Number 1=311-2.21KHRCT-ND, TempCo="100 ppm/C", Tolerance_%=1%, Value2=0.1W, Value_Code=2k21, ValueDisplayed=2.21k
R23: library part CMP-0023152-5, "RES, 4.75 k, 1%, 0.1 W, 0603", Manufacturer=Yageo, Power_W=100mW, Supplier Part Number 1=311-4.75KHRCT-ND, TempCo="100 ppm/C", Tolerance_%=1%, Value2=0.1W, Value_Code=4k75, ValueDisplayed=4.75k
R24: library part CMP-0022892-5, "RES, 1.80 k, 1%, 0.1 W, 0603", Manufacturer=Yageo, Power_W=100mW, Supplier Part Number 1=311-1.80KHRCT-ND, TempCo="100 ppm/C", Tolerance_%=1%, Value2=0.1W, Value_Code=1k80, ValueDisplayed=1.80k
R25: library part CMP-0022763-5, "RES, 11.0 k, 1%, 0.1 W, 0603", Manufacturer=Yageo, Power_W=100mW, Supplier Part Number 1=311-11.0KHRCT-ND, TempCo="100 ppm/C", Tolerance_%=1%, Value2=0.1W, Value_Code=11k0, ValueDisplayed=11.0k
R26 R27: library part CMP-0015723-3, "RES, 7.50, 1%, 1 W, AEC-Q200 Grade 0, 2512", Manufacturer=Vishay-Dale, Power_W=1W, Supplier Part Number 1=541-7.50AFCT-ND, TempCo="100 ppm/C", Tolerance_%=1%, Value_Code=7R50, ValueDisplayed=7.50
R29 R30 R33 R34: library part CMP-0015821-2, "RES, 0.004, 1%, 1 W, 2512", Manufacturer=Panasonic, Power_W=1W, Supplier Part Number 1=P4.0NDCT-ND, TempCo=ppm/C, Tolerance_%=1%, Value_Code=4L000, ValueDisplayed=0.004
R31 R32 R35 R36: library part CMP-0021901-2, "RES, 2.20, 1%, 0.125 W, 0805", Manufacturer="Yageo America", Power_W=125mW, Supplier Part Number 1=311-2.20CRCT-ND, TempCo="200 ppm/C", Tolerance_%=1%, Value2=0.125W, Value_Code=2R20, ValueDisplayed=2.20
R38: library part CMP-0022901-4, "RES, 200 k, 1%, 0.1 W, 0603", Manufacturer=Yageo, Power_W=100mW, Supplier Part Number 1=311-200KHRCT-ND, TempCo="100 ppm/C", Tolerance_%=1%, Value2=0.1W, Value_Code=200k
T1 T2: library part CMP-0055442-1, "Terminal 50A Lug", Manufacturer=Panduit, Supplier Part Number 1=CB35-36-CY-ND, Voltage_V=600V
U1 U2: library part CMP-0085413-1, "2.2-MHz Wide Input Nonsynchronous Boost, Sepic, Flyback Controller, DSS0012B (WSON-12)", Alternate Manufacturer="Texas Instruments", Alternate PartNumber=LM5155DSST
U3: library part CMP-0066783-1, "150-mA, 30-V, Ultra-Low IQ, Wide Input Low-Dropout Regulator with Reverse Current Protection, DBV0005A (SOT-23-5)", Alternate Manufacturer="Texas Instruments", Alternate PartNumber=TPS70950DBVT
U4: library part CMP-0068884-3, "CMOS Timer, 8-pin Narrow SOIC", Manufacturer="Texas Instruments"
U5: library part CMP-0042683-1, "550 uA/Ch, 3 MHz, Rail-to-Rail Output Operational Amplifier, 2.7 to 16 V, -40 to 125 degC, 5-pin SOT23 (DBV5), Green (RoHS & no Sb/Br)", Manufacturer="Texas Instruments", Rating=Catalog, Total Supply Voltage(Max)(+5V is 5, +/-5V is 10)=16, Total Supply Voltage(Min)(+5V is 5, +/-5V is 10)=2.7

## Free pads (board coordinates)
  round 236.22 hole 125.98: 1(204.72,204.72) 1(204.72,3338.58) 1(4913.39,204.72) 1(4913.39,3338.58)

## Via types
v1: diameter 30, hole 15, Top Layer to Bottom Layer, 279 vias
v2: diameter 32, hole 16, Top Layer to Bottom Layer, 56 vias
v3: diameter 22, hole 10, Top Layer to Bottom Layer, tented both sides, 23 vias
v4: diameter 19.68, hole 7.87, Top Layer to Bottom Layer, 6 vias

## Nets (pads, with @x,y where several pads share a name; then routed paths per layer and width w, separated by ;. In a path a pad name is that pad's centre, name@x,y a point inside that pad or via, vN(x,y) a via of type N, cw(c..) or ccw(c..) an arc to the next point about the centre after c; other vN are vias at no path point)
5V: C30.1 C31.1 R24.2 U3.5 U4.4 U4.8 | length 730.2
  Top Layer w25: U4.8@2176.72,2235 2218,2235 2230,2247 ; R24.2@2230.5,2090 2230.5,2246.5 2230,2247 ; U3.5@2326.13,2537.4 2394.09,2537.4 C30.1@2402,2529.5 2419.5,2529.5 2451,2498 2451,2415 2421,2385 U4.4@2391.28,2385 2368,2385 2230,2247
AGND1: C13.2 C14.2 C15.2 NT1.2 R11.1 R13.1 U1.7 | length 468.8
  Top Layer w10: R11.1@2640.51,2239 R13.1@2640.51,2369 2715.51,2444 C14.2@2735.51,2444 ; C15.2@2735.51,2509 C14.2@2735.51,2444 ; U1.7@2793.11,2368.21 2798.5,2373.61 NT1.2@2798.5,2394 ; 2793.08,2402.9 2793.08,2385.1 2793.08,2388.58 NT1.2@2798.5,2394 ; C14.2@2735.51,2444 2735.51,2431.99 2773.5,2394 NT1.2@2798.5,2394
AGND2: C28.2 C35.2 C36.2 NT2.2 R21.1 R39.1 U2.7 | length 642.6
  Top Layer w10: R21.1@2238.5,1060.94 R39.1@2238.5,1190.94 ; C28.2@2238.5,1125.94 R39.1@2238.5,1190.94 ; U2.7@2387.6,1135.15 2387.6,1156.54 2392,1160.94 2392,1223.5 C35.2@2407.5,1239 2407.5,1306 C36.2@2406.5,1307 2366.5,1267 2314.57,1267 R39.1@2238.5,1190.94 ; U2.7@2393,1135 2393,1186
BIAS1: C6.1 R1.1 R2.2 U1.1 | length 207.4
  Top Layer w10: U1.1@2867.91,2269.79 2890,2247.7 C6.1@2890,2214
  Top Layer w30: C6.1@2890,2214 2889.01,2213.01 R1.1@2889.01,2142 R2.2@2959.02,2142
BIAS2: C21.1 R14.2 R28.1 U2.1 | length 213.6
  Top Layer w10: U2.1@2462.4,1036.72 2462.4,995.03 C21.1@2481.5,975.94
  Top Layer w30: R28.1@2416.5,905.94 R14.2@2488.5,905.94 2481.5,912.94 C21.1@2481.5,975.94
CLK1: C33.1 Q7.1 R5.1 R23.2 U4.3 | length 538.8
  Top Layer w20: U4.3@2391.28,2335 2471.5,2335 R23.2@2476,2330.5 2632.5,2174 R5.1@2640.51,2174 2640.51,2129.51 2604.5,2093.5 C33.1@2545,2093.5 2541.75,2090.24 Q7.1@2478.4,2090.24
CLK2: Q7.3 R17.1 R24.1 | length 1559.8
  Top Layer w20: R17.1@2233.5,990.94 R17.1@2238.5,995.94 2173,1061.44 2173,1210 2383,1420 2383,1498 2529,1644 2529,1768 2293.5,2003.5 R24.1@2293.5,2090 2305,2090 2399.24,1995.76 Q7.3@2441,1995.76
COMP1: C14.1 R12.2 U1.6 | length 150.5
  Top Layer w10: U1.6@2867.91,2368.21 R12.2@2867.91,2446.6
  Top Layer w20: R12.2@2867.01,2447.5 R12.2@2868.5,2449
  Top Layer w30: C14.1@2798.5,2444 2863.5,2444 R12.2@2867.01,2447.5
COMP2: C35.1 R40.2 U2.6 | length 192.2
  Top Layer w10: U2.6@2462.4,1135.15 2462.4,1230.91 C35.1@2470.5,1239
  Top Layer w25: C35.1@2470.5,1239 2474,1242.5 R40.2@2554,1242.5
CS1: R6.1 U1.5 | length 141.2
  Top Layer w10: U1.5@2867.91,2348.53 2883.03,2348.53 2948.5,2414 R6.1@2982.01,2414
CS2: R18.1 U2.5 | length 119.1
  Top Layer w10: U2.5@2462.4,1115.46 2503.03,1115.46 R18.1@2558.5,1170.94
FB: R9.1 R13.2 U1.8 | length 155.1
  Top Layer w10: R13.2@2703.5,2369 2738.5,2369 v3(2743.5,2364) 2758.98,2348.53 U1.8@2793.11,2348.53
  Bottom Layer w20: v3(2743.5,2364) 2781,2326.5 R9.1@2781,2322.5
FB2: R37.1 R38.1 R39.2 U2.8 | length 254.9
  Top Layer w10: R39.2@2301.5,1190.94 2316.05,1190.94 v3(2329.98,1177) 2341,1165.98 2341,1137 2362.54,1115.46 U2.8@2387.6,1115.46
  Bottom Layer w10: R38.1@2241.5,1224 R37.1@2304.5,1224 2329.98,1198.52 v3(2329.98,1177)
GT1: Q1.1 Q3.1 U1.3 | length 611.2
  Top Layer w10: U1.3@2867.91,2309.16 2918.35,2309.16 2923.19,2314 v3(2923.5,2314)
  Top Layer w20: v3(2923,2479) 2923,2572.34 Q1.1@2997.91,2647.24 3045.15,2600 3100.66,2600 Q3.1@3147.91,2647.24
  Bottom Layer w10: v3(2923,2479) 2923.5,2478.5 v3(2923.5,2314)
GT2: Q4.1 Q6.1 U2.3 | length 724
  Top Layer w10: U2.3@2462.4,1076.09 2494.84,1076.09 v3@2510,1060.94
  Top Layer w20: Q4.1@2826.6,883.76 2898.84,956 v3(2916,956) 2931,956 2961.6,925.4 Q6.1@2961.6,883.76
  Bottom Layer w10: v3(2509,1062) 2754,1062 2860,956 v3(2916,956)
NetC5_1: C5.1 Q1.3 R3.1 | length 383.7
  Top Layer w30: Q1.3@2960.5,2552.76 3033.76,2479.5 R3.1@3234.5,2479.5 3234.5,2556 C5.1@3236.5,2558
NetC8_1: C8.1 R26.1
NetC12_1: C12.1 R6.2 R7.1 | length 134.1
  Top Layer w30: C12.1@3045,2349 R6.2@3045,2414 3046.5,2415.5 R7.1@3113.5,2415.5
NetC15_1: C15.1 R12.1 | length 69.1
  Top Layer w30: C15.1@2798.5,2509 2800,2510.5 R12.1@2867.01,2510.5
NetC20_1: C20.1 Q4.3 R15.1 | length 217.1
  Top Layer w20: R15.1@2745,963.5 2849.25,963.5 Q4.3@2864,978.24 2864,1025 C20.1@2896,1057
NetC23_1: C23.1 R27.1
NetC27_1: C27.1 R18.2 R19.1 | length 130
  Top Layer w30: R18.2@2621.5,1170.94 C27.1@2621.5,1105.94 2621.5,1045.94 R19.1@2625,1042.43
NetC32_1: C32.1 R23.1 U4.2 U4.6 | length 438
  Top Layer w20: U4.6@2176.72,2335 2177.72,2336 v3(2220,2336) ; v3(2344,2287) 2346,2285 U4.2@2391.28,2285 2429,2285 2446.5,2267.5 R23.1@2476,2267.5 2472.5,2264 C32.1@2472.5,2159
  Bottom Layer w20: v3(2220,2336) 2295,2336 v3(2344,2287)
NetC34_1: C34.1 J2.2 R25.2 U3.3 | length 2834.2
  Top Layer w20: J2.2@114,2643 252,2505 1190.82,2505 1646.82,2961 1930,2961 2214,2676 2214,2615.5 R25.2@2222.5,2607 2272,2607 ; U3.3@2217.87,2462.6 2259.6,2462.6 2272,2475 2272,2607 ; C34.1@2328.5,2607 2272,2607
NetC36_1: C36.1 R40.1 | length 85.1
  Top Layer w25: C36.1@2469.5,1307 2471,1305.5 R40.1@2554,1305.5
NetC37_1: C37.1 C38.1 R41.2 U5.4 | length 209.3
  Top Layer w20: R41.2@2147,1639.5 2210,1639.5 C37.1@2211,1640.5 2280.01,1640.5 2282.5,1643 2282.5,1676.92 2282.5,1713.77 U5.4@2283.6,1714.87
NetC40_1: C40.1 R42.2 U5.3 | length 153.3
  Top Layer w20: R42.2@2147,1863.5 2148,1862.5 C40.1@2211,1862.5 2244.24,1862.5 U5.3@2283.6,1823.13
NetD1_1: D1.1 D1.3 L1.2 Q2.2 Q8.2 R26.2 | length 4751.5
  Top Layer w20: L1.2@1779.09,3169.8 1976.29,3367 2363,3367 ; Q2.2@2360,2805 2360,3364 2363,3367 ; Q8.2@3345,2805 3345,3365 3347,3367 ; D1.1@4230,2795 4230,3276 4234,3280 ; D1.3@4430,2795 4430,3084 4234,3280 ; 2363,3367 3347,3367 ; 3347,3367 4147,3367 4234,3280
NetD2_1: D2.1 D2.3 L2.1 Q5.2 Q9.2 R27.2 | length 5045.6
  Top Layer w15: L2.1@1760.16,375.2 1979.35,156 2360,156 ; Q5.2@2360,740 2360,156 ; Q9.2@3345,740 3345,156 ; D2.3@4230,750 4230,157 4231,156 ; D2.1@4430,750 4430,278 4308,156 4231,156 ; 2360,156 3345,156 ; 3345,156 4231,156
NetD3_1: D3.1 Q1.2 Q3.2 R4.1 | length 361.1
  Top Layer w30: R4.1@2859,2772 2888.47,2742.53 2923,2742.53 ; Q1.2@2923.1,2647.24 2923.1,2742.43 2923,2742.53 ; Q3.2@3073.1,2647.24 2977.82,2742.53 D3.1@2959,2742.53 2923,2742.53
NetD3_2: D3.2 R4.2 R31.1 R32.1 | length 324.5
  Top Layer w20: R31.1@2755,2851 2858,2851 R4.2@2859,2852 2878.47,2871.47 D3.2@2959,2871.47 3043.53,2871.47 R32.1@3063,2852
NetD4_1: D4.1 Q4.2 Q6.2 R16.1 | length 370.9
  Top Layer w30: R16.1@2826,759 2907.53,759 D4.1@2939,790.47 ; Q4.2@2901.4,883.76 2901.4,828.07 D4.1@2939,790.47 ; Q6.2@3036.4,883.76 2943.11,790.47 D4.1@2939,790.47
NetD4_2: D4.2 R16.2 R35.1 R36.1 | length 333.5
  Top Layer w15: R35.1@2726,679 R16.2@2826,679 2921.53,679 D4.2@2939,661.53 2956.47,679 R36.1@3045,679
NetJ2_3: J2.3 R22.1 | length 94.9
  Top Layer w30: J2.3@114,2543 118.5,2538.5 R22.1@118.5,2450
NetQ2_1: Q2.1 R31.2 | length 601.5
  Top Layer w30: Q2.1@2260,2805 2260,2742 2298,2704 2688,2704 R31.2@2755,2771
NetQ2_3: Q2.3 Q8.3 R7.2 R8.2 | length 480.4
  Top Layer w20: R7.2@3120,2359 3131,2359 3142,2370 3173,2401 v3(3173,2404)
  Bottom Layer w20: v3(3173,2404) 3173,2556 3170,2559 3232.14,2621.14 R8.2@3395,2621.14
NetQ5_1: Q5.1 R35.2 | length 273.9
  Top Layer w30: Q5.1@2460,740 2479,759 R35.2@2726,759
NetQ5_3: Q5.3 Q9.3 R19.2 R20.2 | length 436.9
  Top Layer w20: R19.2@2625,974.44 2630.56,980 v3(2664,980)
  Bottom Layer w20: v3(2664,980) 2731,913 2987,913 3001,899 3001,874
NetQ8_1: Q8.1 R32.2 | length 195.7
  Top Layer w30: R32.2@3063,2772 3212,2772 Q8.1@3245,2805
NetQ9_1: Q9.1 R36.2 | length 492.1
  Top Layer w30: R36.2@3045,759 3124,838 3379,838 3445,772 Q9.1@3445,740
NetR5_2: R5.2 U1.12 | length 132.9
  Top Layer w10: R5.2@2703.5,2174 2703.5,2180.18 U1.12@2793.11,2269.79
NetR9_2: R9.2 R10.1 | length 67
  Bottom Layer w20: R10.1@2781,2192.5 R9.2@2781,2259.5
NetR17_2: R17.2 U2.12 | length 103
  Top Layer w10: R17.2@2301.5,995.94 2335,995.94 2375.79,1036.72 U2.12@2387.6,1036.72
